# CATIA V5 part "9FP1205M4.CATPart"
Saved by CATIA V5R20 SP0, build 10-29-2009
Part number: 9FP1205M4
Revision: ANY
Definition: UNKNOWN
Nomenclature: 9FP1205M4
Source: Unknown
Bounding box of the stored display mesh (mm): x -5.752 to 5.752, y 0 to 5, z -5.9 to 5.9
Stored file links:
  C:\Users\Utente\Desktop\IO LAVORO\3D X SITO CF\CUMSA\3D files PW\pw060622\pw060622_ejection\9FP1205M4.CATPart
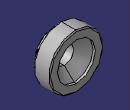
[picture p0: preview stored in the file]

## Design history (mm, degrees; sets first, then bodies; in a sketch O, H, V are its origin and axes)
Body1 "Redondeo2" (main body)
  Solid1: solid without history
